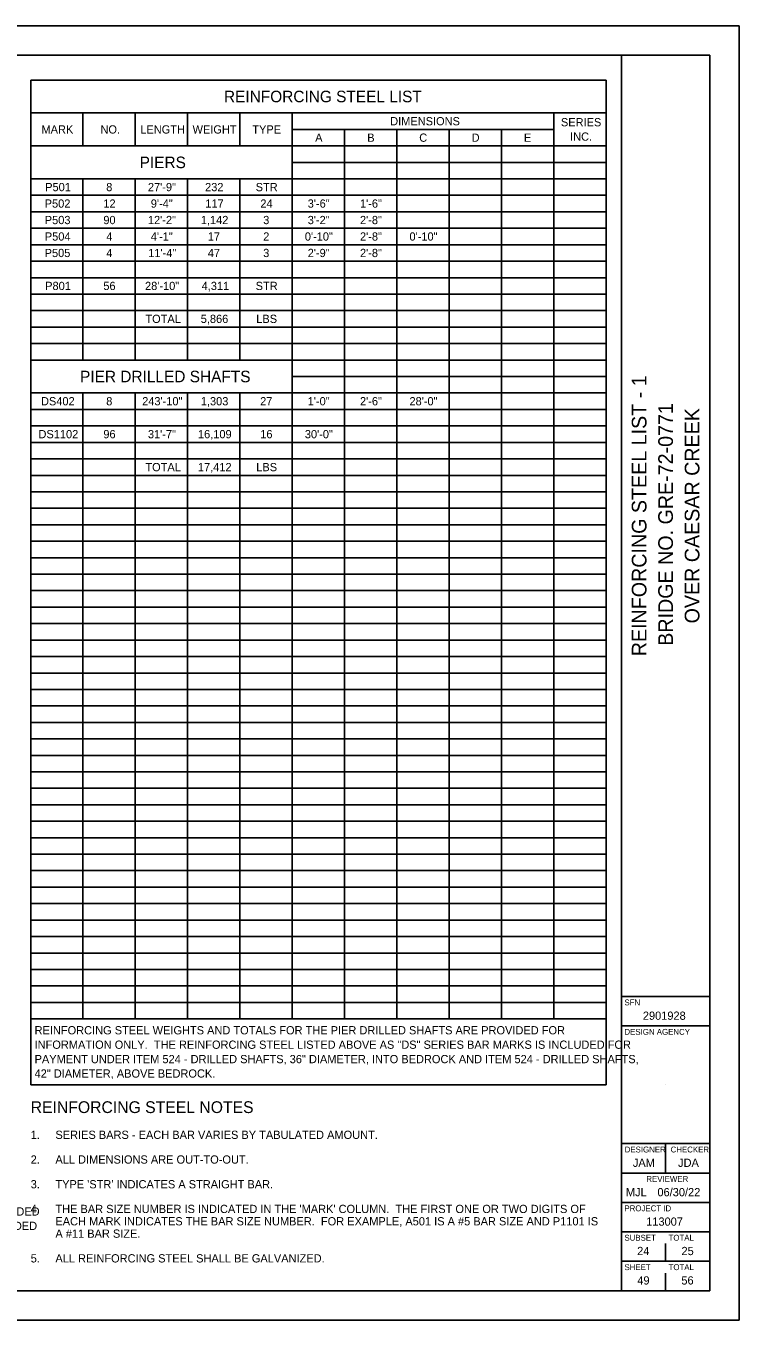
# Model space of a CAD drawing. Extents: x 0 to 34, y 0 to 22.
# Drawn here: x 21.87 to 34, y 0 to 22 of the extents above; entities that cross this region are included whole.
import ezdxf

# ---------------------------------------------------------------- set-up
doc = ezdxf.new("R2010")
doc.units = 0
for name, color, linetype in [('BR_P_Gen_Text', 7, 'Continuous'), ('Default', 7, 'Continuous'), ('SH_Border', 7, 'Continuous'), ('SH_Cut_Line', 7, 'Continuous'), ('SH_Data', 7, 'Continuous')]:
    doc.layers.add(name, color=color, linetype=linetype)

msp = doc.modelspace()

# ---------------------------------------------------------------- linework, layer by layer
at = {"layer": 'Default'}
for p, q in [((21.955, 21.08), (31.738, 21.08)), ((21.955, 21.08), (21.955, 4)), ((31.738, 21.08), (31.738, 4)), ((21.955, 20.52), (31.738, 20.52)), ((22.844, 20.52), (22.844, 19.96)), ((23.734, 20.52), (23.734, 19.96)), ((24.623, 20.52), (24.623, 19.96)), ((25.512, 20.52), (25.512, 19.96)), ((26.402, 20.52), (26.402, 5.12)), ((30.849, 20.52), (30.849, 5.12)), ((26.402, 20.24), (30.849, 20.24)), ((27.291, 20.24), (27.291, 5.12)), ((28.181, 20.24), (28.181, 5.12)), ((29.07, 20.24), (29.07, 5.12)), ((29.959, 20.24), (29.959, 5.12)), ((21.955, 19.96), (31.738, 19.96)), ((26.402, 19.68), (31.738, 19.68)), ((21.955, 19.4), (26.402, 19.4)), ((22.844, 19.4), (22.844, 16.32)), ((23.734, 19.4), (23.734, 16.32)), ((24.623, 19.4), (24.623, 16.32)), ((25.512, 19.4), (25.512, 16.32)), ((26.402, 19.4), (31.738, 19.4)), ((21.955, 19.12), (31.738, 19.12)), ((21.955, 18.84), (31.738, 18.84)), ((21.955, 18.56), (31.738, 18.56)), ((21.955, 18.28), (31.738, 18.28)), ((21.955, 18), (31.738, 18)), ((21.955, 17.72), (31.738, 17.72)), ((21.955, 17.44), (31.738, 17.44)), ((21.955, 17.16), (31.738, 17.16)), ((21.955, 16.88), (31.738, 16.88)), ((21.955, 16.6), (31.738, 16.6)), ((21.955, 16.32), (26.402, 16.32)), ((26.402, 16.32), (31.738, 16.32)), ((26.402, 16.04), (31.738, 16.04)), ((21.955, 15.76), (26.402, 15.76)), ((22.844, 15.76), (22.844, 5.12)), ((23.734, 15.76), (23.734, 5.12)), ((24.623, 15.76), (24.623, 5.12)), ((25.512, 15.76), (25.512, 5.12)), ((26.402, 15.76), (31.738, 15.76)), ((21.955, 15.48), (31.738, 15.48)), ((21.955, 15.2), (31.738, 15.2)), ((21.955, 14.92), (31.738, 14.92)), ((21.955, 14.64), (31.738, 14.64)), ((21.955, 14.36), (31.738, 14.36)), ((21.955, 14.08), (31.738, 14.08)), ((21.955, 13.8), (31.738, 13.8)), ((21.955, 13.52), (31.738, 13.52)), ((21.955, 13.24), (31.738, 13.24)), ((21.955, 12.96), (31.738, 12.96)), ((21.955, 12.68), (31.738, 12.68)), ((21.955, 12.4), (31.738, 12.4)), ((21.955, 12.12), (31.738, 12.12)), ((21.955, 11.84), (31.738, 11.84)), ((21.955, 11.56), (31.738, 11.56)), ((21.955, 11.28), (31.738, 11.28)), ((21.955, 11), (31.738, 11)), ((21.955, 10.72), (31.738, 10.72)), ((21.955, 10.44), (31.738, 10.44)), ((21.955, 10.16), (31.738, 10.16)), ((21.955, 9.88), (31.738, 9.88)), ((21.955, 9.6), (31.738, 9.6)), ((21.955, 9.32), (31.738, 9.32)), ((21.955, 9.04), (31.738, 9.04)), ((21.955, 8.76), (31.738, 8.76)), ((21.955, 8.48), (31.738, 8.48)), ((21.955, 8.2), (31.738, 8.2)), ((21.955, 7.92), (31.738, 7.92)), ((21.955, 7.64), (31.738, 7.64)), ((21.955, 7.36), (31.738, 7.36)), ((21.955, 7.08), (31.738, 7.08)), ((21.955, 6.8), (31.738, 6.8)), ((21.955, 6.52), (31.738, 6.52)), ((21.955, 6.24), (31.738, 6.24)), ((21.955, 5.96), (31.738, 5.96)), ((21.955, 5.68), (31.738, 5.68)), ((21.955, 5.4), (31.738, 5.4)), ((21.955, 5.12), (31.738, 5.12)), ((21.955, 4), (31.738, 4))]:
    msp.add_line(p, q, dxfattribs=at)
at = {"layer": 'SH_Border'}
for p, q in [((32, 0.5), (32, 21.5)), ((32, 5.5), (33.5, 5.5)), ((32, 5), (33.5, 5)), ((32, 3), (33.5, 3)), ((32.75, 3), (32.75, 2.5)), ((32, 2.5), (33.5, 2.5)), ((32, 2), (33.5, 2)), ((32, 1.5), (33.5, 1.5)), ((32, 1), (33.5, 1))]:
    msp.add_line(p, q, dxfattribs=at)
msp.add_lwpolyline([(1.5, 21.5), (33.5, 21.5), (33.5, 0.5), (1.5, 0.5)], close=True, dxfattribs=at)
at = {"layer": 'SH_Cut_Line'}
msp.add_lwpolyline([(0, 0), (34, 0), (34, 22), (0, 22)], close=True, dxfattribs=at)
at = {"layer": 'SH_Data'}
for p, q in [((32.75, 4), (32.75, 4)), ((32.75, 1), (32.75, 1.3)), ((32.375, 0.675), (32.375, 0.675)), ((32.75, 0.5), (32.75, 0.8))]:
    msp.add_line(p, q, dxfattribs=at)

# ---------------------------------------------------------------- texts
at = {"layer": 'BR_P_Gen_Text'}
for s, height, p in [('REINFORCING STEEL NOTES', 0.2, (21.955, 3.52)), ('1.', 0.14, (21.955, 3.08)), ('SERIES BARS - EACH BAR VARIES BY TABULATED AMOUNT.', 0.14, (22.375, 3.08)), ('2.', 0.14, (21.955, 2.66)), ('ALL DIMENSIONS ARE OUT-TO-OUT.', 0.14, (22.375, 2.66)), ('3.', 0.14, (21.955, 2.24)), ("TYPE 'STR' INDICATES A STRAIGHT BAR.", 0.14, (22.375, 2.24)), ('4.', 0.14, (21.955, 1.82)), ("THE BAR SIZE NUMBER IS INDICATED IN THE 'MARK' COLUMN.  THE FIRST ONE OR TWO DIGITS OF ", 0.14, (22.375, 1.82)), ('A #11 BAR SIZE.', 0.14, (22.375, 1.4)), ('EACH MARK INDICATES THE BAR SIZE NUMBER.  FOR EXAMPLE, A501 IS A #5 BAR SIZE AND P1101 IS ', 0.14, (22.375, 1.61)), ('5.', 0.14, (21.955, 0.98)), ('ALL REINFORCING STEEL SHALL BE GALVANIZED.', 0.14, (22.375, 0.98))]:
    msp.add_text(s, height=height, dxfattribs=at).set_placement(p)
at = {"layer": 'Default'}
for s, height, p in [('REINFORCING STEEL LIST', 0.196, (25.241, 20.702)), ('MARK', 0.14, (22.138, 20.17)), ('NO.', 0.14, (23.141, 20.17)), ('LENGTH', 0.14, (23.818, 20.17)), ('WEIGHT', 0.14, (24.707, 20.17)), ('TYPE', 0.14, (25.723, 20.17)), ('DIMENSIONS', 0.14, (28.067, 20.31)), ('SERIES ', 0.14, (30.97, 20.293)), ('A', 0.14, (26.792, 20.03)), ('B', 0.14, (27.677, 20.03)), ('C', 0.14, (28.561, 20.03)), ('D', 0.14, (29.452, 20.03)), ('E', 0.14, (30.341, 20.03)), ('INC.', 0.14, (31.126, 20.048)), ('PIERS', 0.196, (23.807, 19.582)), ('P501', 0.14, (22.201, 19.19)), ('8', 0.14, (23.239, 19.19)), ('27\'-9"', 0.14, (23.948, 19.19)), ('232', 0.14, (24.92, 19.19)), ('STR', 0.14, (25.78, 19.19)), ('P502', 0.14, (22.193, 18.91)), ('12', 0.14, (23.19, 18.91)), ('9\'-4"', 0.14, (23.997, 18.91)), ('117', 0.14, (24.924, 18.91)), ('24', 0.14, (25.86, 18.91)), ('3\'-6"', 0.14, (26.665, 18.91)), ('1\'-6"', 0.14, (27.554, 18.91)), ('P503', 0.14, (22.194, 18.63)), ('90', 0.14, (23.19, 18.63)), ('12\'-2"', 0.14, (23.948, 18.63)), ('1,142', 0.14, (24.847, 18.63)), ('3', 0.14, (25.908, 18.63)), ('3\'-2"', 0.14, (26.665, 18.63)), ('2\'-8"', 0.14, (27.554, 18.63)), ('P504', 0.14, (22.195, 18.35)), ('4', 0.14, (23.241, 18.35)), ('4\'-1"', 0.14, (23.997, 18.35)), ('17', 0.14, (24.966, 18.35)), ('2', 0.14, (25.908, 18.35)), ('0\'-10"', 0.14, (26.616, 18.35)), ('2\'-8"', 0.14, (27.554, 18.35)), ('0\'-10"', 0.14, (28.395, 18.35)), ('P505', 0.14, (22.192, 18.07)), ('4', 0.14, (23.241, 18.07)), ('11\'-4"', 0.14, (23.954, 18.07)), ('47', 0.14, (24.966, 18.07)), ('3', 0.14, (25.908, 18.07)), ('2\'-9"', 0.14, (26.665, 18.07)), ('2\'-8"', 0.14, (27.554, 18.07)), ('P801', 0.14, (22.201, 17.51)), ('56', 0.14, (23.19, 17.51)), ('28\'-10"', 0.14, (23.899, 17.51)), ('4,311', 0.14, (24.861, 17.51)), ('STR', 0.14, (25.78, 17.51)), ('TOTAL', 0.14, (23.905, 16.95)), ('5,866', 0.14, (24.846, 16.95)), ('LBS', 0.14, (25.79, 16.95)), ('PIER DRILLED SHAFTS', 0.196, (22.794, 15.942)), ('DS402', 0.14, (22.13, 15.55)), ('8', 0.14, (23.239, 15.55)), ('243\'-10"', 0.14, (23.85, 15.55)), ('1,303', 0.14, (24.847, 15.55)), ('27', 0.14, (25.856, 15.55)), ('1\'-0"', 0.14, (26.665, 15.55)), ('2\'-6"', 0.14, (27.554, 15.55)), ('28\'-0"', 0.14, (28.395, 15.55)), ('DS1102', 0.14, (22.087, 14.99)), ('96', 0.14, (23.19, 14.99)), ('31\'-7"', 0.14, (23.948, 14.99)), ('16,109', 0.14, (24.799, 14.99)), ('16', 0.14, (25.858, 14.99)), ('30\'-0"', 0.14, (26.616, 14.99)), ('TOTAL', 0.14, (23.905, 14.43)), ('17,412', 0.14, (24.798, 14.43)), ('LBS', 0.14, (25.79, 14.43)), ('REINFORCING STEEL WEIGHTS AND TOTALS FOR THE PIER DRILLED SHAFTS ARE PROVIDED FOR ', 0.14, (22.021, 4.857)), ('INFORMATION ONLY.  THE REINFORCING STEEL LISTED ABOVE AS "DS" SERIES BAR MARKS IS INCLUDED FOR ', 0.14, (22.021, 4.612)), ('PAYMENT UNDER ITEM 524 - DRILLED SHAFTS, 36" DIAMETER, INTO BEDROCK AND ITEM 524 - DRILLED SHAFTS, ', 0.14, (22.021, 4.367)), ('42" DIAMETER, ABOVE BEDROCK.', 0.14, (22.021, 4.122)), ('REINFORCING STEEL WEIGHTS AND TOTALS FOR THE FORWARD ABUTMENT DRILLED SHAFTS ARE PROVIDED ', 0.14, (11.924, 1.777)), ('FOR INFORMATION ONLY.  THE REINFORCING STEEL LISTED ABOVE AS "DS" SERIES BAR MARKS IS INCLUDED ', 0.14, (11.924, 1.532))]:
    msp.add_text(s, height=height, dxfattribs=at).set_placement(p)
at = {"layer": 'SH_Data'}
for s, p in [('REINFORCING STEEL LIST - 1', (32.425, 11.285)), ('BRIDGE NO. GRE-72-0771', (32.875, 11.463)), ('OVER CAESAR CREEK', (33.325, 11.843))]:
    msp.add_text(s, height=0.25, rotation=90, dxfattribs=at).set_placement(p)
for s, height, p in [('SFN', 0.1, (32.05, 5.35)), ('2901928', 0.14, (32.363, 5.105)), ('DESIGN AGENCY', 0.1, (32.05, 4.85)), ('DESIGNER', 0.1, (32.054, 2.85)), ('CHECKER', 0.1, (32.835, 2.85)), ('JAM', 0.14, (32.193, 2.605)), ('JDA', 0.14, (32.962, 2.605)), ('REVIEWER', 0.1, (32.422, 2.35)), ('MJL', 0.14, (32.075, 2.105)), ('06/30/22', 0.14, (32.611, 2.105)), ('PROJECT ID', 0.1, (32.05, 1.85)), ('113007', 0.14, (32.42, 1.605)), ('SUBSET', 0.1, (32.05, 1.35)), ('TOTAL', 0.1, (32.8, 1.35)), ('24', 0.14, (32.266, 1.105)), ('25', 0.14, (33.02, 1.105)), ('SHEET', 0.1, (32.05, 0.85)), ('TOTAL', 0.1, (32.8, 0.85)), ('49', 0.14, (32.269, 0.605)), ('56', 0.14, (33.018, 0.605))]:
    msp.add_text(s, height=height, dxfattribs=at).set_placement(p)

doc.saveas('drawing.dxf')
